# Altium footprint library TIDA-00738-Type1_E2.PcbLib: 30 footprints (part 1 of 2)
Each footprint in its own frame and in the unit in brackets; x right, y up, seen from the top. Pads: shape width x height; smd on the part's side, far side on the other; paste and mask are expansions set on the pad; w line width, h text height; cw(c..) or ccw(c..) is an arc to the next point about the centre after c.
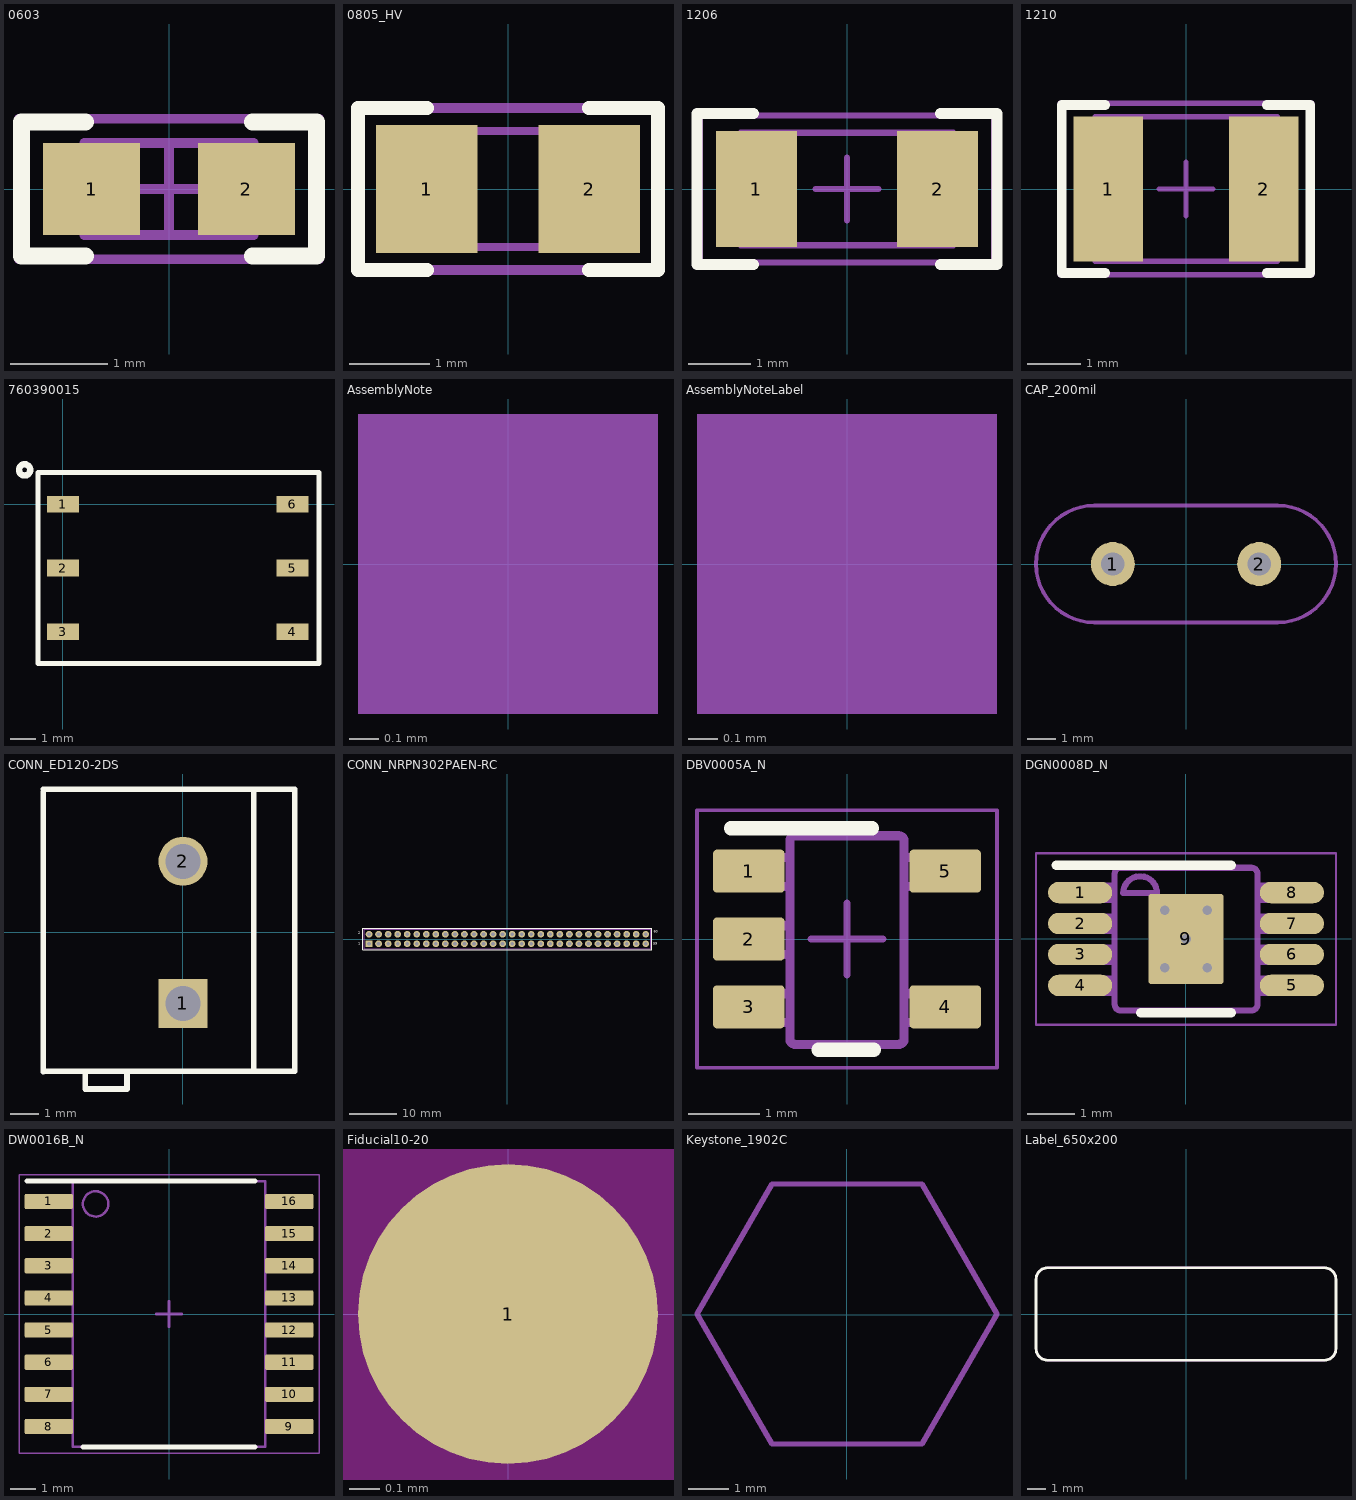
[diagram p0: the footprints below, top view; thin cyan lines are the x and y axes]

## 0603 [mm] "0603 from SM-752 data"
height 1
pads (2):
  rect 1x0.95 smd: 1(-0.8,0) 2(0.8,0)
Top Overlay:
  lines w0.178: -0.864,-0.691 -1.524,-0.691 -1.524,0.693 -0.864,0.693 ; 0.864,-0.691 1.524,-0.691 1.524,0.693 0.864,0.693
Mechanical 5:
  lines w0.1: -1.55,-0.725 -1.55,0.725 1.55,0.725 1.55,-0.725 -1.55,-0.725
  text ".Designator" at 1.168,0.406 h0.76
Mechanical 13:
  lines w0.1: -0.55,-0.475 -0.55,0.475 ; 0.55,-0.475 0.55,0.475 ; -0.875,-0.475 0.875,-0.475 0.875,0.475 -0.875,0.475 -0.875,-0.475
Mechanical 15:
  lines w0.1: -0.475,0 0.475,0 ; 0,-0.475 0,0.475 ; -1.55,-0.725 1.55,-0.725 1.55,0.725 -1.55,0.725 -1.55,-0.725
3D body: height 1, standoff 0, extent -0.874,-0.474 -0.551,0.474
3D body: height 1, standoff 0, extent -0.549,-0.474 0.549,0.474
3D body: height 1, standoff 0, extent 0.551,-0.474 0.874,0.474

## 0805_HV [mil] "0805 with 30mil clearance between pads"
height 57.09
pads (2):
  rect 50x63 smd: 1(-40,0) 2(40,0)
Top Overlay:
  lines w7: -40,-40 -74,-40 -74,0 -74,40 -40,40 ; 40,-40 74,-40 74,0 74,40 40,40
Mechanical 5:
  lines w5: -74,-40 74,-40 74,40 -74,40 -74,-40
  text ".Designator" at -64,-17 h30
Mechanical 13:
  lines w3.94: -25.59,-28.54 -25.59,28.54 ; 25.59,-28.54 25.59,28.54 ; -43.31,-28.54 43.31,-28.54 43.31,28.54 -43.31,28.54 -43.31,-28.54
3D body: height 57.09, standoff 0, extent -43.29,-28.52 -25.61,28.52
3D body: height 57.09, standoff 0, extent -25.57,-28.52 25.57,28.52
3D body: height 57.09, standoff 0, extent 25.61,-28.52 43.29,28.52

## 1206 [mm] "1206 from SM-752 data"
height 1.35
pads (2):
  rect 1.3x1.85 smd: 1(-1.45,0) 2(1.45,0)
Top Overlay:
  lines w0.178: -1.5,-1.21 -2.4,-1.21 -2.4,1.21 -1.5,1.21 ; 1.5,-1.21 2.4,-1.21 2.4,1.21 1.5,1.21
Mechanical 5:
  lines w0.1: -1.7,-0.9 1.7,-0.9 1.7,0.9 -1.7,0.9 -1.7,-0.9
  text ".Designator" at 0.98,0.432 h0.76
Mechanical 13:
  lines w0.1: -1.2,-0.9 -1.2,0.9 ; 1.2,-0.9 1.2,0.9 ; -1.7,-0.9 1.7,-0.9 1.7,0.9 -1.7,0.9 -1.7,-0.9
Mechanical 15:
  lines w0.1: -0.5,0 0.5,0 ; 0,-0.5 0,0.5 ; -2.35,-1.175 2.35,-1.175 2.35,1.175 -2.35,1.175 -2.35,-1.175
3D body: height 1.35, standoff 0, extent -1.699,-0.899 -1.201,0.899
3D body: height 1.35, standoff 0, extent -1.199,-0.899 1.199,0.899
3D body: height 1.35, standoff 0, extent 1.201,-0.899 1.699,0.899

## 1210 [mm] "1210 from SM-752 data"
height 1.35
pads (2):
  rect 1.3x2.7 smd: 1(-1.45,0) 2(1.45,0)
Top Overlay:
  lines w0.178: -1.511,-1.568 -2.316,-1.568 -2.316,1.568 -1.511,1.568 ; 1.511,-1.568 2.316,-1.568 2.316,1.568 1.511,1.568
Mechanical 5:
  lines w0.1: -1.7,-1.35 1.7,-1.35 1.7,1.35 -1.7,1.35 -1.7,-1.35
  text ".Designator" at -1.041,-0.398 h0.76
Mechanical 13:
  lines w0.1: -1.2,-1.35 -1.2,1.35 ; 1.2,-1.35 1.2,1.35 ; -1.7,-1.35 -1.7,1.35 1.7,1.35 1.7,-1.35 -1.7,-1.35
Mechanical 15:
  lines w0.1: -0.5,0 0.5,0 ; 0,-0.5 0,0.5 ; -2.35,-1.6 -2.35,1.6 2.35,1.6 2.35,-1.6 -2.35,-1.6
3D body: height 1.35, standoff 0, extent -1.699,-1.349 -1.201,1.349
3D body: height 1.35, standoff 0, extent -1.199,-1.349 1.199,1.349
3D body: height 1.35, standoff 0, extent 1.201,-1.349 1.699,1.349

## 760390015 [mm]
height 0.85
pads (6):
  rect 1.27x0.66 smd: 1(0,0) 2(0,-2.54) 3(0,-5.08) 4(9.14,-5.08) 5(9.14,-2.54) 6(9.14,0)
Top Overlay:
  circle w0.254: c-1.524,1.367 r0.224
  lines w0.2: -1,-6.35 10.2,-6.35 10.2,1.27 -1,1.27 -1,-6.35
3D body: height 4.2, standoff 0.2, extent -1,-6.4 10.2,1.2

## AssemblyNote [mm] "Assembly Note"
Mechanical 5:
  rectangle: -0.508,-0.508 0.508,0.508
  text ".Designator" at -4.191,-0.508 h0.76
  text ".Comment" at 1.143,-0.508 h0.76

## AssemblyNoteLabel [mm] "Assembly Note for PCB Labels"
Mechanical 5:
  rectangle: -0.508,-0.508 0.508,0.508
  text ".Designator" at -4.191,-0.508 h0.76
  text "Install label in silkscreened box after final wash.  Text shall be 8 pt font.  Text shall be per the Label Table in the PDF schematic." at 1.143,-0.508 h0.76

## CAP_200mil [mil]
height 33.46
pads (2):
  round 60 hole 32 mask+5: 1(-100,0) 2(100,0)
Mechanical 5:
  lines w5: -125,-80 cw(c-125,0) -125,80 125,80 cw(c125,0) 125,-80 -125,-80
  text ".Designator" at -35,-15 h30

## CONN_ED120-2DS [mm] "ONSHORE"
height 13
pads (2):
  rect 1.75x1.75 hole 1.25: 1(0,-2.54)
  round 1.75 hole 1.25: 2(0,2.54)
Top Overlay:
  lines w0.2: -5,-4.985 -5,5.015 ; -5,-4.96 4,-4.96 ; -5,5.115 4,5.115 4,-4.885 ; -3.5,-4.96 -3.5,-5.6 -2,-5.6 -2,-4.96 ; 2.525,-4.95 2.525,5.05
Mechanical 5:
  lines w0.1: -5,-4.96 4,-4.96 ; -5,-4.885 -5,5.115 4,5.115 4,-4.885 ; -3.5,-4.96 -3.5,-5.6 -2,-5.6 -2,-4.96 ; 2.525,-4.875 2.525,5.125
  text ".Designator" at -1.27,0.889 h0.76
3D body: height 13, standoff 0, extent -5,-4.985 4,5.115
3D body: height 13.1, standoff -2.5, extent -0.496,-3.039 0.5,-2.041
3D body: height 13.1, standoff -2.5, extent -0.496,2.041 0.5,3.039
3D body: height 5.7, standoff 4.3, extent -0.85,1.846 4.15,3.24
3D body: height 5.7, standoff 4.3, extent -0.875,-3.204 4.125,-1.81
3D body: height 13, standoff 0, extent -3.5,-5.6 -2,-4.925

## CONN_NRPN302PAEN-RC [mil]
height 33.46
pads (60):
  rect 56x56 hole 31: 1(-1141.73,-39.37)
  round 56 hole 31: 2(-1141.73,39.37) 3(-1062.99,-39.37) 4(-1062.99,39.37) 5(-984.25,-39.37) 6(-984.25,39.37) 7(-905.51,-39.37) 8(-905.51,39.37) 9(-826.77,-39.37) 10(-826.77,39.37) 11(-748.03,-39.37) 12(-748.03,39.37) 13(-669.29,-39.37) 14(-669.29,39.37) 15(-590.55,-39.37) 16(-590.55,39.37) 17(-511.81,-39.37) 18(-511.81,39.37) 19(-433.07,-39.37) 20(-433.07,39.37) 21(-354.33,-39.37) 22(-354.33,39.37) 23(-275.59,-39.37) 24(-275.59,39.37) 25(-196.85,-39.37) 26(-196.85,39.37) 27(-118.11,-39.37) 28(-118.11,39.37) 29(-39.37,-39.37) 30(-39.37,39.37) 31(39.37,-39.37) 32(39.37,39.37) 33(118.11,-39.37) 34(118.11,39.37) 35(196.85,-39.37) 36(196.85,39.37) 37(275.59,-39.37) 38(275.59,39.37) 39(354.33,-39.37) 40(354.33,39.37) 41(433.07,-39.37) 42(433.07,39.37) 43(511.81,-39.37) 44(511.81,39.37) 45(590.55,-39.37) 46(590.55,39.37) 47(669.29,-39.37) 48(669.29,39.37) 49(748.03,-39.37) 50(748.03,39.37) 51(826.77,-39.37) 52(826.77,39.37) 53(905.51,-39.37) 54(905.51,39.37) 55(984.25,-39.37) 56(984.25,39.37) 57(1062.99,-39.37) 58(1062.99,39.37) 59(1141.73,-39.37) 60(1141.73,39.37)
Top Overlay:
  lines w6: -1192.91,-90.55 1192.91,-90.55 1192.91,90.55 -1192.91,90.55 -1192.91,-90.55
  text "60" at 1208,42 h35
  text "59" at 1203,-55 h35
  text "2" at -1233,30 h35
  text "1" at -1230,-57 h35
Mechanical 5:
  lines w6: -1181.1,-78.74 -1181.1,78.74 1181.1,78.74 1181.1,-78.74 -1181.1,-78.74
  text ".Designator" at -27,-17 h30
3D body: height 220.47, standoff 110.24, extent -1181.1,-78.74 1181.1,78.74

## DBV0005A_N [mm] "SOT23, 5-Leads, Body 2.9x1.6mm, Pitch 0.95mm, Lead Span 2.8mm, IPC Medium Density"
height 1.45
pads (5):
  rrect17% 1x0.6 smd: 1(-1.375,0.95) 2(-1.375,0) 3(-1.375,-0.95) 4(1.375,-0.95) 5(1.375,0.95)
Top Overlay:
  lines w0.2: -1.625,1.55 0.35,1.55 ; -0.4,-1.55 0.375,-1.55
Mechanical 5:
  lines w0.127: -0.801,1.371 cw(c-0.725,1.37) -0.725,1.446 ; -0.801,1.37 -0.801,-1.399 -0.801,-1.4 ccw(c-0.725,-1.399) -0.725,-1.475 ; -0.801,1.37 -0.801,1.371 ; -0.725,-1.475 -0.725,-1.475 ; -0.725,-1.475 0.723,-1.475 0.724,-1.475 ccw(c0.723,-1.399) 0.799,-1.4 0.799,-1.399 0.799,1.37 ; -0.725,1.446 0.723,1.446 0.724,1.446 cw(c0.723,1.37) 0.799,1.371 ; -0.725,1.446 -0.725,1.446 ; 0.799,1.37 0.799,1.371 ; -1.423,-1.167 -1.199,-1.167 -1.105,-1.167 -1.088,-1.167 -0.835,-1.167 -0.801,-1.167 -0.801,-0.767 -0.835,-0.767 -1.088,-0.767 -1.105,-0.767 -1.199,-0.767 -1.423,-0.767 -1.423,-1.167 ; -1.423,-0.215 -1.199,-0.215 -1.105,-0.215 -1.088,-0.215 -0.835,-0.215 -0.801,-0.215 -0.801,0.186 -0.835,0.186 -1.088,0.186 -1.105,0.186 -1.199,0.186 -1.423,0.186 -1.423,-0.215 ; -1.423,0.738 -1.199,0.738 -1.105,0.738 -1.088,0.738 -0.835,0.738 -0.801,0.738 -0.801,1.138 -0.835,1.138 -1.088,1.138 -1.105,1.138 -1.199,1.138 -1.423,1.138 -1.423,0.738 ; 0.799,-1.167 0.799,-0.767 0.834,-0.767 1.087,-0.767 1.103,-0.767 1.198,-0.767 1.422,-0.767 1.422,-1.167 1.198,-1.167 1.103,-1.167 1.087,-1.167 0.834,-1.167 0.799,-1.167 ; 0.799,0.738 0.799,1.138 0.834,1.138 1.087,1.138 1.103,1.138 1.198,1.138 1.422,1.138 1.422,0.738 1.198,0.738 1.103,0.738 1.087,0.738 0.834,0.738 0.799,0.738
  text ".Designator" at -0.25,0.95 h0.76
Mechanical 15:
  lines w0.05: -2.1,-1.8 2.1,-1.8 2.1,1.8 -2.1,1.8 -2.1,-1.8
  lines w0.1: -0.5,0 0.5,0 ; 0,-0.5 0,0.5
3D body: height 1.09, standoff 0, extent -1.422,-1.461 1.423,1.46

## DGN0008D_N [mm] "TSOP, 8-Leads, Body 3x3mm, Pitch 0.65mm, Thermal Pad 1.89x1.57mm, IPC Medium Density"
height 1.1
pads (9):
  rrect100% 1.35x0.45 smd: 1(-2.225,0.975) 2(-2.225,0.325) 3(-2.225,-0.325) 4(-2.225,-0.975) 5(2.225,-0.975) 6(2.225,-0.325) 7(2.225,0.325) 8(2.225,0.975)
  rrect6% 1.57x1.89 smd: 9(0,0)
via -0.45,0.6 diameter 0.5 hole 0.2
via -0.45,-0.6 diameter 0.5 hole 0.2
via 0.45,-0.6 diameter 0.5 hole 0.2
via 0.45,0.6 diameter 0.5 hole 0.2
via 0,0 diameter 0.5 hole 0.2
Top Overlay:
  lines w0.2: -2.725,1.55 0.95,1.55 ; -0.95,-1.55 0.95,-1.55
Mechanical 5:
  lines w0.127: -2.45,-1.131 -2.45,-0.826 -2.21,-0.826 -2.09,-0.826 -2.087,-0.826 -1.784,-0.826 -1.498,-0.826 -1.498,-1.131 -1.784,-1.131 -2.087,-1.131 -2.09,-1.131 -2.21,-1.131 -2.45,-1.131 ; -2.45,-0.48 -2.45,-0.175 -2.21,-0.175 -2.09,-0.175 -2.087,-0.175 -1.784,-0.175 -1.498,-0.175 -1.498,-0.48 -1.784,-0.48 -2.087,-0.48 -2.09,-0.48 -2.21,-0.48 -2.45,-0.48 ; -2.45,0.17 -2.45,0.475 -2.21,0.475 -2.09,0.475 -2.087,0.475 -1.784,0.475 -1.498,0.475 -1.498,0.17 -1.784,0.17 -2.087,0.17 -2.09,0.17 -2.21,0.17 -2.45,0.17 ; -2.45,0.82 -2.45,1.125 -2.21,1.125 -2.09,1.125 -2.087,1.125 -1.784,1.125 -1.498,1.125 -1.498,0.82 -1.784,0.82 -2.087,0.82 -2.09,0.82 -2.21,0.82 -2.45,0.82 ; -1.497,-1.377 ccw(c-1.37,-1.374) -1.373,-1.501 -1.371,-1.501 1.373,-1.501 1.375,-1.501 ccw(c1.373,-1.374) 1.5,-1.377 1.5,-1.374 1.5,1.369 1.5,1.372 ccw(c1.373,1.369) 1.375,1.496 1.373,1.496 -1.371,1.496 -1.373,1.496 ccw(c-1.37,1.369) -1.497,1.372 -1.498,1.369 -1.498,-1.374 -1.497,-1.377 ; -1.32,0.962 cw(c-0.964,0.962) -0.609,0.962 -1.32,0.962 ; 1.5,-1.131 1.786,-1.131 2.089,-1.131 2.093,-1.131 2.213,-1.131 2.452,-1.131 2.452,-0.826 2.213,-0.826 2.093,-0.826 2.089,-0.826 1.786,-0.826 1.5,-0.826 1.5,-1.131 ; 1.5,-0.48 1.786,-0.48 2.089,-0.48 2.093,-0.48 2.213,-0.48 2.452,-0.48 2.452,-0.175 2.213,-0.175 2.093,-0.175 2.089,-0.175 1.786,-0.175 1.5,-0.175 1.5,-0.48 ; 1.5,0.17 1.786,0.17 2.089,0.17 2.093,0.17 2.213,0.17 2.452,0.17 2.452,0.475 2.213,0.475 2.093,0.475 2.089,0.475 1.786,0.475 1.5,0.475 1.5,0.17 ; 1.5,0.82 1.786,0.82 2.089,0.82 2.093,0.82 2.213,0.82 2.452,0.82 2.452,1.125 2.213,1.125 2.093,1.125 2.089,1.125 1.786,1.125 1.5,1.125 1.5,0.82
  text ".Designator" at 0.45,-0.6 h0.76
Mechanical 15:
  lines w0.05: -3.15,-1.8 3.15,-1.8 3.15,1.8 -3.15,1.8 -3.15,-1.8
  lines w0.1: -0.5,0 0.5,0 ; 0,-0.5 0,0.5
3D body: height 1.1, standoff 0, extent -2.46,-1.5 2.46,1.5

## DW0016B_N [mm] "SOIC, 16-Leads, Body 10.5x7.6mm, Pitch 1.27mm, IPC Medium Density"
height 2.65
pads (16):
  rrect17% 1.9x0.6 smd: 1(-4.75,4.445) 2(-4.75,3.175) 3(-4.75,1.905) 4(-4.75,0.635) 5(-4.75,-0.635) 6(-4.75,-1.905) 7(-4.75,-3.175) 8(-4.75,-4.445) 9(4.75,-4.445) 10(4.75,-3.175) 11(4.75,-1.905) 12(4.75,-0.635) 13(4.75,0.635) 14(4.75,1.905) 15(4.75,3.175) 16(4.75,4.445)
Top Overlay:
  lines w0.2: -5.6,5.25 3.4,5.25 ; -3.4,-5.25 3.4,-5.25
Mechanical 5:
  text ".Designator" at -0.381,0.5 h0.76
Mechanical 13:
  circle w0.1: c-2.9,4.35 r0.5
  lines w0.1: -3.8,-5.25 3.8,-5.25 3.8,5.25 -3.8,5.25 -3.8,-5.25
Mechanical 15:
  lines w0.05: -5.925,-5.5 5.925,-5.5 5.925,5.5 -5.925,5.5 -5.925,-5.5
  lines w0.1: -0.5,0 0.5,0 ; 0,-0.5 0,0.5
3D body: height 2.59, standoff 0, extent -5.167,-5.15 5.167,5.15

## Fiducial10-20 [mm]
pads (1):
  round 1 smd mask+0.5: 1(0,0)
Top Layer keep-out:
  circle w1.178: c0,0 r0.5

## Keystone_1902C [mm] "Hex Standoff, 4-40 threaded, nylon"
height 12.7
Mechanical 5:
  lines w0.127: -3.69,0.012 -1.843,-3.188 1.852,-3.188 3.7,0.012 1.852,3.212 -1.843,3.212 -3.69,0.012
  text ".Designator" at -1.524,-0.508 h0.76
3D body: height 12.73, standoff 0.03, extent -3.682,-3.2 3.708,3.2

## Label_650x200 [mm] "Thermal Transfer Label"
height 0.025
Top Overlay:
  lines w0.152: -8.255,-1.905 ccw(c-7.62,-1.905) -7.62,-2.54 7.62,-2.54 ccw(c7.62,-1.905) 8.255,-1.905 8.255,1.905 ccw(c7.62,1.905) 7.62,2.54 -7.62,2.54 ccw(c-7.62,1.905) -8.255,1.905 -8.255,-1.905
Mechanical 5:
  lines w0.127: -8.255,-1.905 ccw(c-7.62,-1.905) -7.62,-2.54 7.62,-2.54 ccw(c7.62,-1.905) 8.255,-1.905 8.255,1.905 ccw(c7.62,1.905) 7.62,2.54 -7.62,2.54 ccw(c-7.62,1.905) -8.255,1.905 -8.255,-1.905
  text ".Designator" at -1.524,-0.508 h0.76
3D body: height 0.03, standoff 0, extent -8.268,-2.553 8.268,2.553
